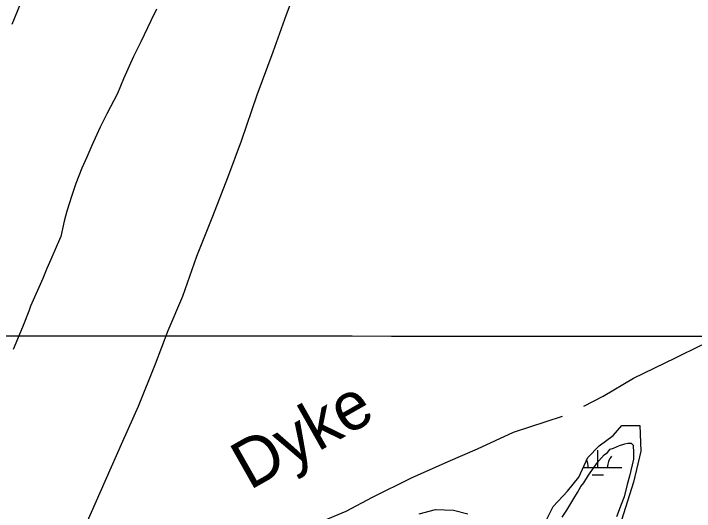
# Model space of a CAD drawing. Extents: x 3250478 to 3288318, y 788638 to 816472.
# Drawn here: x 3268510 to 3269923, y 805775 to 806808 of the extents above; entities that cross this region are included whole.
import ezdxf

# ---------------------------------------------------------------- set-up
doc = ezdxf.new("R2010")
doc.units = 0
for name, color, linetype in [('V-DTCH-CNTR', 7, 'Continuous'), ('V-GRID-MAJR', 7, 'Continuous'), ('V-RIVR-IDEN', 7, 'Continuous'), ('V-SITE-VEGE', 7, 'Continuous'), ('V-TOPO-SHOR', 7, 'Continuous'), ('V-WETL-SWMP', 7, 'Continuous')]:
    doc.layers.add(name, color=color, linetype=linetype)

msp = doc.modelspace()

# ---------------------------------------------------------------- linework, layer by layer
at = {"layer": 'V-DTCH-CNTR'}
for points in [[(3269221.139, 807347.267), (3269204.622, 807263.145), (3269185.701, 807179.865), (3269173.736, 807112.998), (3269164.68, 807070.969), (3269152.085, 807019.314), (3269132.969, 806965.948), (3269110.216, 806898.618), (3269075.357, 806805.929), (3269048.014, 806728.251), (3269014.504, 806639.216), (3268981.906, 806543.914), (3268953.39, 806467.362), (3268922.1950000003, 806387.4), (3268889.29, 806304.04), (3268860.356, 806221.287), (3268829.8880000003, 806149.832), (3268803.272, 806080.751), (3268768.146, 805993.015), (3268735.849, 805919.934), (3268698.867, 805836.9450000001)], [(3268698.867, 805836.9450000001), (3268660.196, 805749.409), (3268628.4590000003, 805679.613), (3268603.983, 805643.585), (3268574.057, 805595.684), (3268542.234, 805545.094), (3268521.7290000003, 805509.5800000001), (3268514.366, 805486.345), (3268512.103, 805464.884), (3268510.912, 805443.002), (3268511.426, 805424.6)]]:
    msp.add_lwpolyline(points, dxfattribs=at)
at = {"layer": 'V-GRID-MAJR'}
msp.add_spline([(3254645.228, 806146.921), (3259882.848, 806143.493), (3265120.469, 806140.826), (3270358.09, 806138.922), (3275595.711, 806137.779), (3280833.333, 806137.398), (3286070.954, 806137.779), (3286070.955, 806137.779)], degree=3, dxfattribs=at)
at = {"layer": 'V-SITE-VEGE'}
for points in [[(3268806.458, 806817.998), (3268794.603, 806793.385), (3268773.426, 806750.099), (3268758.179, 806719.5430000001), (3268737.8540000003, 806672.862), (3268725.153, 806642.308), (3268703.127, 806600.718), (3268689.573, 806572.707), (3268671.786, 806534.514), (3268661.626, 806510.7490000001), (3268651.4620000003, 806487.834), (3268638.762, 806455.584), (3268630.296, 806430.971), (3268620.14, 806398.721), (3268614.219, 806377.506), (3268607.4560000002, 806346.108), (3268599.836, 806328.286), (3268587.134, 806297.732), (3268578.663, 806279.061), (3268570.1950000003, 806258.689), (3268544.787, 806200.9770000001), (3268541.4020000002, 806190.792), (3268529.548, 806161.088), (3268521.08, 806140.718), (3268508.378, 806111.012)], [(3269648.107, 805763.219), (3269658.2770000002, 805777.6510000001), (3269672.68, 805802.2660000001), (3269680.305, 805814.15), (3269687.082, 805826.883), (3269693.015, 805834.524), (3269703.185, 805850.652), (3269721.828, 805876.969), (3269724.372, 805880.362), (3269735.392, 805892.251), (3269742.1750000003, 805897.344), (3269748.108, 805904.139), (3269754.893, 805906.689), (3269760.83, 805909.2390000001), (3269767.6180000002, 805911.791), (3269778.644, 805915.193), (3269784.5810000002, 805916.894), (3269791.3680000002, 805916.9010000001), (3269795.616, 805912.661)], [(3269795.616, 805912.661), (3269796.4760000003, 805896.539), (3269796.486, 805883.8150000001), (3269788.0300000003, 805848.174), (3269782.953, 805831.2000000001), (3269777.034, 805805.743), (3269771.107, 805789.617), (3269760.947, 805764.157)]]:
    msp.add_lwpolyline(points, dxfattribs=at)
at = {"layer": 'V-TOPO-SHOR'}
for points in [[(3269693.0870000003, 805993.696), (3269733.438, 806014.127), (3269796.38, 806051.458), (3269883.823, 806093.96), (3269936.815, 806119.882), (3269992.062, 806139.5160000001), (3270056.4960000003, 806163.508), (3270115.208, 806188.5530000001), (3270192.789, 806224.549), (3270270.721, 806260.817), (3270362.705, 806303.581), (3270453.362, 806340.884), (3270532.955, 806373.975), (3270592.37, 806399.657)], [(3268523.968, 805446.991), (3268561.188, 805458.278), (3268581.0330000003, 805469.4230000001), (3268605.978, 805489.305), (3268642.833, 805510.831), (3268690.75, 805536.483), (3268738.416, 805561.3250000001), (3268782.272, 805585.028), (3268823.264, 805604.402), (3268870.731, 805625.501), (3268930.502, 805651.099), (3268985.972, 805678.046), (3269032.406, 805697.074), (3269085.181, 805725.218), (3269145.4450000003, 805753.054), (3269199.828, 805775.9720000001), (3269254.286, 805804.5920000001), (3269335.449, 805844.573), (3269411.6380000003, 805878.6730000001), (3269472.64, 805905.274), (3269547.038, 805939.873), (3269648.819, 805973.104)]]:
    msp.add_lwpolyline(points, dxfattribs=at)
at = {"layer": 'V-WETL-SWMP'}
for p, q in [((3269722.4330527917, 805866.5596668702), (3269722.4442713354, 805902.5594089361)), ((3269691.9866716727, 805866.568523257), (3269772.432294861, 805866.5451228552)), ((3269710.428425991, 805851.1322679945), (3269734.428062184, 805851.1252868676))]:
    msp.add_line(p, q, dxfattribs=at)
for points in [[(3268559.4590000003, 806916.683), (3268506.19, 806785.763)], [(3269612.434, 805750.633), (3269629.733, 805785.223), (3269659.178, 805817.386), (3269682.678, 805846.171), (3269701.447, 805887.324), (3269724.772, 805911.159), (3269754.503, 805932.55), (3269772.4930000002, 805953.461), (3269809.411, 805953.783), (3269811.899, 805899.857), (3269796.105, 805836.144), (3269767.586, 805743.756)], [(3269351.21, 805770.199), (3269385.145, 805779.035), (3269423.068, 805777.5210000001), (3269452.792, 805770.291)]]:
    msp.add_lwpolyline(points, dxfattribs=at)
for centre, radius, start, end in [((3269777.6752994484, 805867.0183975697), 35.246287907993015, 139.2115164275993, 180.75517476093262), ((3269667.191102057, 805867.0505357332), 35.24628790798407, 359.21150708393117, 25.260714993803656)]:
    msp.add_arc(centre, radius, start, end, dxfattribs=at)

# ---------------------------------------------------------------- texts
at = {"layer": 'V-RIVR-IDEN'}
msp.add_text('Dyke', height=99.99980199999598, rotation=29.512682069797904, dxfattribs=at).set_placement((3268999.4465267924, 805818.1862081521))

doc.saveas('drawing.dxf')
